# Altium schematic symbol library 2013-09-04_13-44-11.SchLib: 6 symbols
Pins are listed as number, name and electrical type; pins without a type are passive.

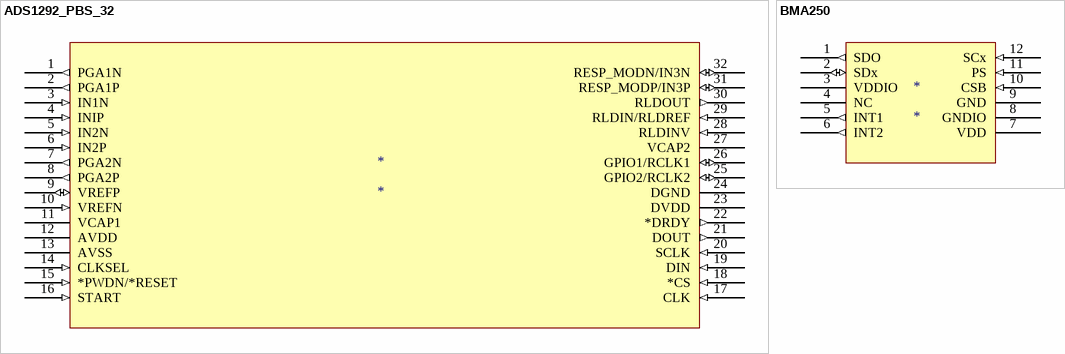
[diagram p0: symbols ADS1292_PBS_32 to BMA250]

## ADS1292_PBS_32
designator *
footprint PBS32
pins: 1 PGA1N (out), 2 PGA1P (out), 3 IN1N (in), 4 INIP (in), 5 IN2N (in), 6 IN2P (in), 7 PGA2N (out), 8 PGA2P (out), 9 VREFP (io), 10 VREFN (in), 11 VCAP1, 12 AVDD, 13 AVSS, 14 CLKSEL (in), 15 *PWDN/*RESET (in), 16 START (in), 17 CLK (in), 18 *CS (in), 19 DIN (in), 20 SCLK (in), 21 DOUT (out), 22 *DRDY (out), 23 DVDD, 24 DGND, 25 GPIO2/RCLK2 (io), 26 GPIO1/RCLK1 (io), 27 VCAP2, 28 RLDINV (in), 29 RLDIN/RLDREF (in), 30 RLDOUT (out), 31 RESP_MODP/IN3P (io), 32 RESP_MODN/IN3N (io)

## BMA250
designator *
pins: 1 SDO (out), 2 SDx (io), 3 VDDIO (power), 4 NC, 5 INT1 (out), 6 INT2 (out), 7 VDD (power), 8 GNDIO (power), 9 GND (power), 10 CSB (in), 11 PS (in), 12 SCx (in)

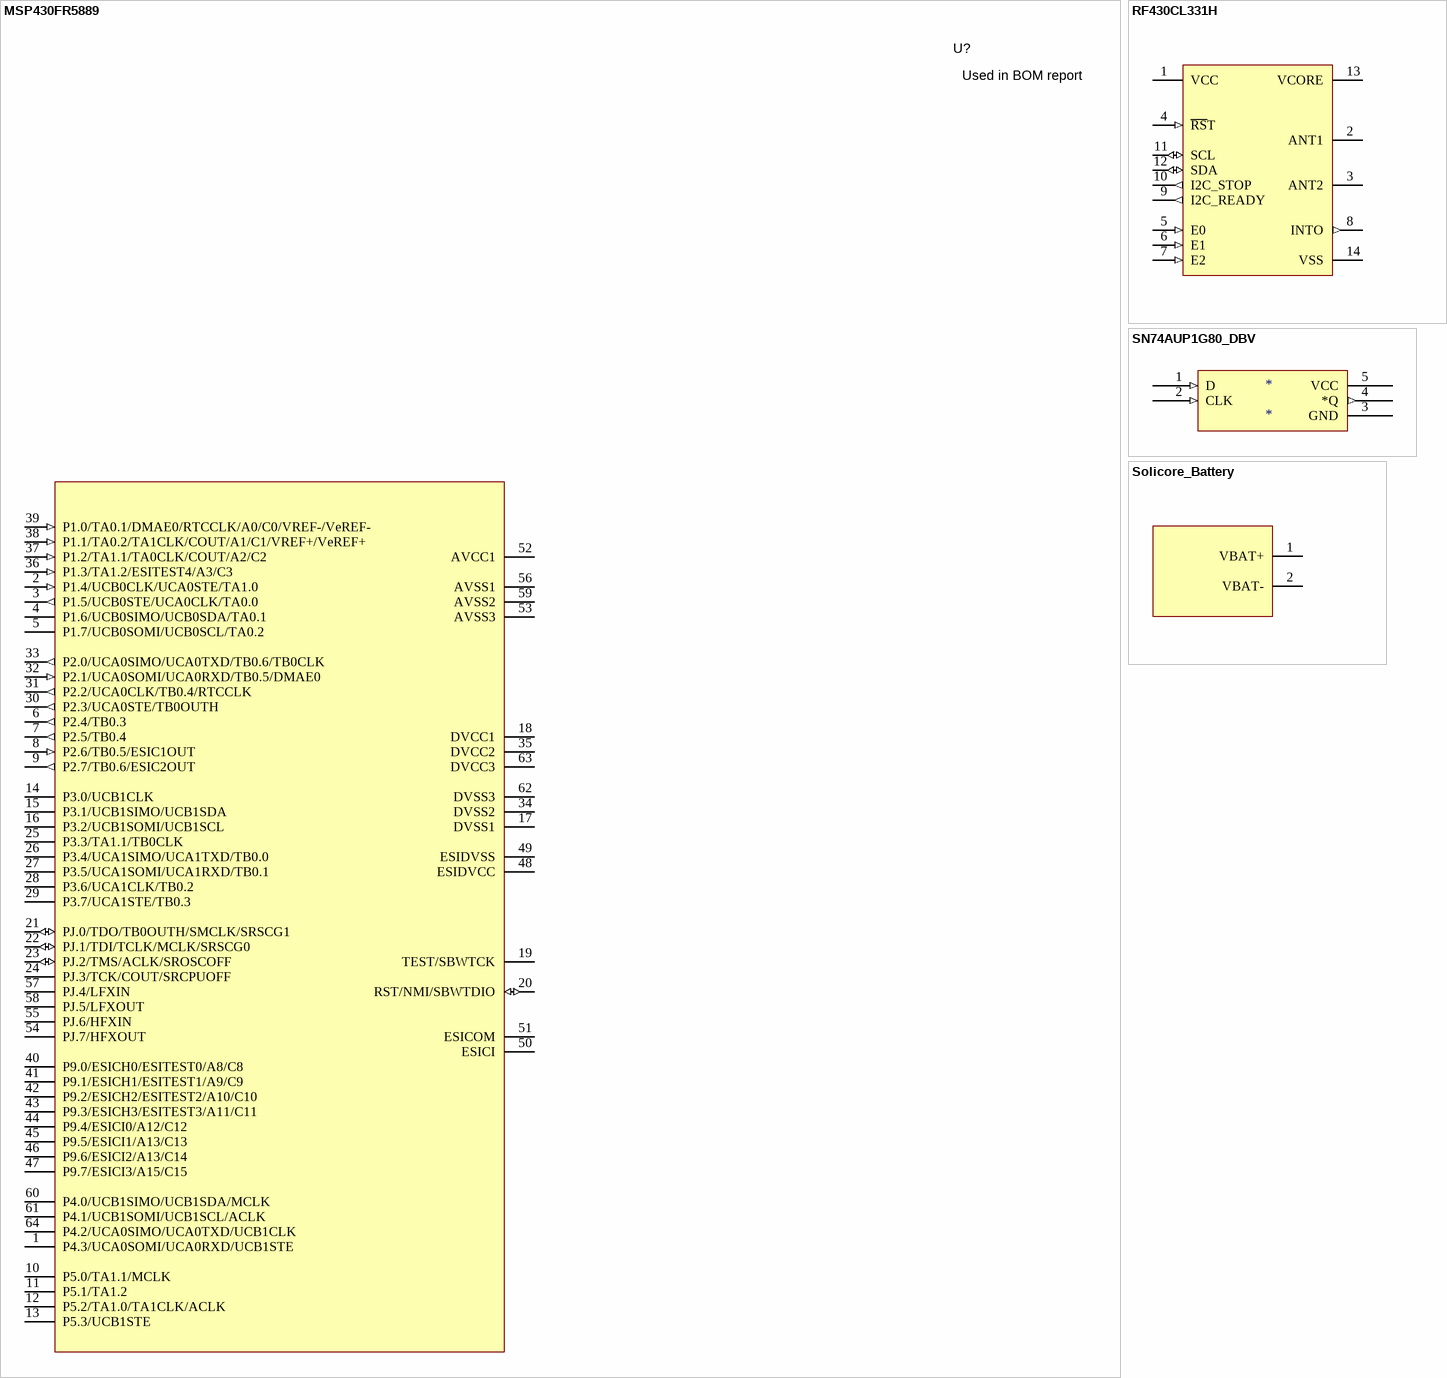
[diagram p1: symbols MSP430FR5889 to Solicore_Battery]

## MSP430FR5889
designator U?, comment Used in BOM report
SymbolVersion: use current date i.e. 2008-05-20; SymbolCreator: Use a-id; CompType: Used in some BOM reports.  Useful for finding later.; U/M: EA, IN, or GM
pins: 1 P4.3/UCA0SOMI/UCA0RXD/UCB1STE, 2 P1.4/UCB0CLK/UCA0STE/TA1.0 (in), 3 P1.5/UCB0STE/UCA0CLK/TA0.0 (out), 4 P1.6/UCB0SIMO/UCB0SDA/TA0.1, 5 P1.7/UCB0SOMI/UCB0SCL/TA0.2, 6 P2.4/TB0.3 (out), 7 P2.5/TB0.4 (out), 8 P2.6/TB0.5/ESIC1OUT (in), 9 P2.7/TB0.6/ESIC2OUT (out), 10 P5.0/TA1.1/MCLK, 11 P5.1/TA1.2, 12 P5.2/TA1.0/TA1CLK/ACLK, 13 P5.3/UCB1STE, 14 P3.0/UCB1CLK, 15 P3.1/UCB1SIMO/UCB1SDA, 16 P3.2/UCB1SOMI/UCB1SCL, 17 DVSS1, 18 DVCC1, 19 TEST/SBWTCK, 20 RST/NMI/SBWTDIO (io), 21 PJ.0/TDO/TB0OUTH/SMCLK/SRSCG1 (io), 22 PJ.1/TDI/TCLK/MCLK/SRSCG0 (io), 23 PJ.2/TMS/ACLK/SROSCOFF (io), 24 PJ.3/TCK/COUT/SRCPUOFF, 25 P3.3/TA1.1/TB0CLK, 26 P3.4/UCA1SIMO/UCA1TXD/TB0.0, 27 P3.5/UCA1SOMI/UCA1RXD/TB0.1, 28 P3.6/UCA1CLK/TB0.2, 29 P3.7/UCA1STE/TB0.3, 30 P2.3/UCA0STE/TB0OUTH (out), 31 P2.2/UCA0CLK/TB0.4/RTCCLK (out), 32 P2.1/UCA0SOMI/UCA0RXD/TB0.5/DMAE0 (in), 33 P2.0/UCA0SIMO/UCA0TXD/TB0.6/TB0CLK (out), 34 DVSS2, 35 DVCC2, 36 P1.3/TA1.2/ESITEST4/A3/C3 (in), 37 P1.2/TA1.1/TA0CLK/COUT/A2/C2 (in), 38 P1.1/TA0.2/TA1CLK/COUT/A1/C1/VREF+/VeREF+ (in), 39 P1.0/TA0.1/DMAE0/RTCCLK/A0/C0/VREF-/VeREF- (in), 40 P9.0/ESICH0/ESITEST0/A8/C8, 41 P9.1/ESICH1/ESITEST1/A9/C9, 42 P9.2/ESICH2/ESITEST2/A10/C10, 43 P9.3/ESICH3/ESITEST3/A11/C11, 44 P9.4/ESICI0/A12/C12, 45 P9.5/ESICI1/A13/C13, 46 P9.6/ESICI2/A13/C14, 47 P9.7/ESICI3/A15/C15, 48 ESIDVCC, 49 ESIDVSS, 50 ESICI, 51 ESICOM, 52 AVCC1, 53 AVSS3, 54 PJ.7/HFXOUT, 55 PJ.6/HFXIN, 56 AVSS1, 57 PJ.4/LFXIN, 58 PJ.5/LFXOUT, 59 AVSS2, 60 P4.0/UCB1SIMO/UCB1SDA/MCLK, 61 P4.1/UCB1SOMI/UCB1SCL/ACLK, 62 DVSS3, 63 DVCC3, 64 P4.2/UCA0SIMO/UCA0TXD/UCB1CLK

## RF430CL331H
designator U?, comment Used in BOM report
SymbolVersion: use current date i.e. 2008-05-20; SymbolCreator: Use a-id; CompType: Used in some BOM reports.  Useful for finding later.; U/M: EA, IN, or GM
pins: 1 VCC, 2 ANT1, 3 ANT2, 4 ~{RS}T (in), 5 E0 (in), 6 E1 (in), 7 E2 (in), 8 INTO (out), 9 I2C_READY (out), 10 I2C_STOP (out), 11 SCL (io), 12 SDA (io), 13 VCORE, 14 VSS

## SN74AUP1G80_DBV
designator *
footprint DBV5
pins: 1 D (in), 2 CLK (in), 3 GND, 4 *Q (out), 5 VCC

## Solicore_Battery
designator U?, comment Used in BOM report
SymbolVersion: use current date i.e. 2008-05-20; SymbolCreator: Use a-id; CompType: Used in some BOM reports.  Useful for finding later.; U/M: EA, IN, or GM
pins: 1 VBAT+ (power), 2 VBAT- (power)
